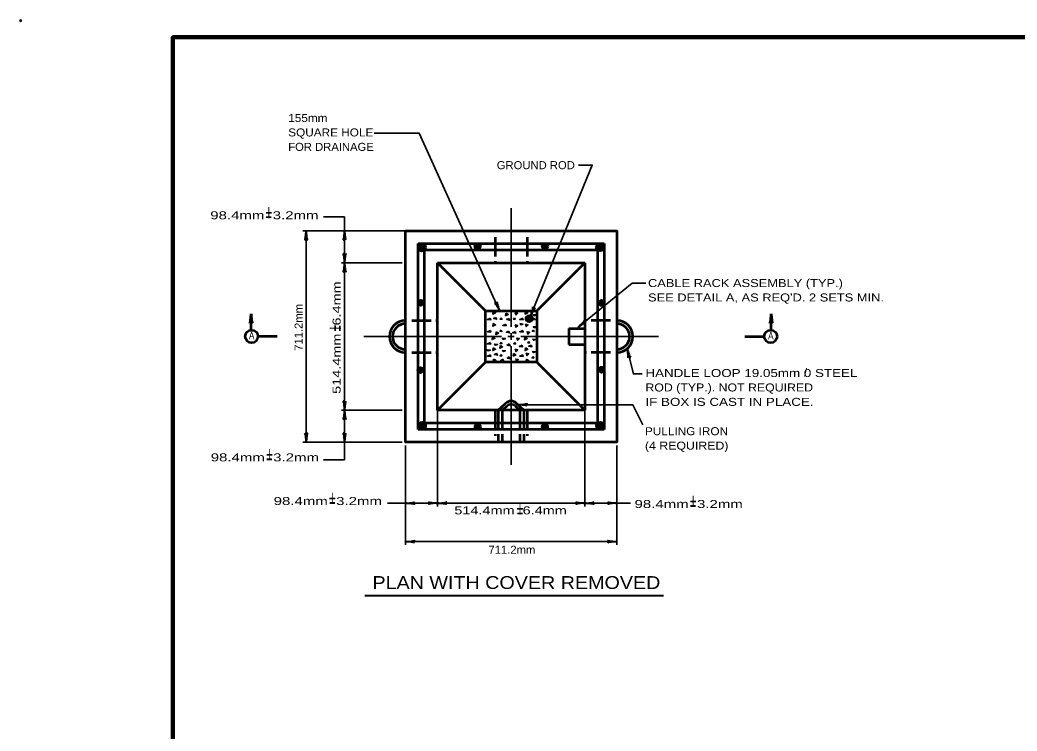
# Model space of a CAD drawing. Extents: x 918 to 1774, y -8 to 536.
# Drawn here: x 918 to 1291.6, y 270 to 536.2 of the extents above; entities that cross this region are included whole.
import ezdxf

# ---------------------------------------------------------------- set-up
doc = ezdxf.new("R2010")
doc.units = 0
doc.header["$LTSCALE"] = 1.2
doc.header["$PDMODE"] = 32
doc.header["$PDSIZE"] = 0.6
doc.linetypes.add('LONG_DASHED', pattern=[7.5, 6, -1.5])
doc.layers.add('1', color=7, linetype='Continuous', lineweight=35)

msp = doc.modelspace()

# ---------------------------------------------------------------- hatches: boundary and pattern name
at = {"layer": '1'}
for points in [[(1069.976, 451.064, 1), (1067.263, 451.064, 1)], [(1090.462, 451.497, 1), (1088.431, 451.497, 1)], [(1115.752, 451.548, 1), (1113.721, 451.548, 1)], [(1136.769, 451.092, 1), (1134.042, 451.092, 1)], [(1069.152, 430.315, 1), (1067.193, 430.315, 1)], [(1136.914, 430.261, 1), (1134.883, 430.261, 1)], [(1110.019, 424.368, 1), (1107.619, 424.368, 1)], [(1069.088, 405.105, 1), (1067.117, 405.105, 1)], [(1136.914, 405.247, 1), (1134.883, 405.247, 1)], [(1069.992, 384.305, 1), (1067.32, 384.305, 1)], [(1090.531, 383.884, 1), (1088.5, 383.884, 1)], [(1115.69, 383.857, 1), (1113.659, 383.857, 1)], [(1136.722, 384.319, 1), (1134.055, 384.319, 1)]]:
    msp.add_hatch(color=256, dxfattribs=at).paths.add_polyline_path(points)

# ---------------------------------------------------------------- linework, layer by layer
for p, q in [((1102.028, 465.692), (1102.028, 421.292)), ((1039.628, 462.502), (1031.703, 462.502)), ((1039.628, 445.292), (1039.628, 462.502)), ((1062.428, 457.292), (1024.028, 457.292)), ((1025.227, 457.292), (1025.227, 378.092)), ((1061.227, 445.292), (1038.428, 445.292)), ((1039.628, 445.292), (1039.628, 390.092)), ((1110.121, 425.918), (1111.379, 425.772)), ((1105.244, 422.513), (1106.502, 422.368)), ((1102.028, 418.892), (1102.028, 416.492)), ((1110.28, 421.408), (1111.525, 421.265)), ((1100.828, 417.692), (1103.227, 417.692)), ((1105.628, 417.692), (1157.227, 417.692)), ((1109.986, 416.71), (1111.237, 416.565)), ((1102.764, 410.352), (1102.899, 411.297)), ((1109.875, 412.12), (1111.122, 411.976)), ((1095.339, 408.3), (1095.476, 409.258)), ((1103.873, 408.962), (1104.072, 408.344)), ((1107.593, 408.265), (1107.728, 409.21)), ((1061.227, 390.092), (1038.428, 390.092)), ((1039.628, 390.092), (1039.628, 371.475)), ((1074.428, 390.092), (1074.428, 354.092)), ((1129.628, 390.092), (1129.628, 354.092)), ((1061.227, 378.092), (1024.028, 378.092)), ((1062.428, 376.892), (1062.428, 339.692)), ((1141.628, 376.892), (1141.628, 339.692)), ((1039.628, 371.475), (1031.703, 371.475)), ((1074.428, 355.292), (1055.658, 355.292)), ((1062.428, 340.892), (1141.628, 340.892))]:
    msp.add_line(p, q, dxfattribs=at)
at = {"layer": '1', "lineweight": 53}
for p, q in [((1067.227, 452.492), (1136.828, 452.492)), ((1067.227, 382.892), (1067.227, 452.492)), ((1136.828, 452.492), (1136.828, 382.892)), ((1069.628, 450.092), (1134.428, 450.092)), ((1069.628, 385.292), (1069.628, 450.092)), ((1134.428, 450.092), (1134.428, 385.292)), ((1074.428, 445.292), (1129.628, 445.292)), ((1074.428, 390.092), (1074.428, 445.292)), ((1074.428, 445.292), (1092.428, 427.292)), ((1129.628, 445.292), (1111.628, 427.292)), ((1004.606, 420.127), (1004.606, 426.127)), ((1199.449, 420.127), (1199.449, 426.127)), ((1123.628, 420.692), (1129.628, 420.692)), ((1123.628, 420.692), (1123.628, 414.692)), ((1014.428, 417.692), (1007.228, 417.692)), ((1123.628, 414.692), (1129.628, 414.692)), ((1189.628, 417.692), (1196.828, 417.692)), ((1074.428, 390.092), (1092.428, 408.092)), ((1129.628, 390.092), (1111.628, 408.092)), ((1097.227, 390.092), (1099.976, 392.669)), ((1106.828, 390.092), (1104.079, 392.669)), ((1129.628, 390.092), (1074.428, 390.092)), ((1098.727, 390.092), (1100.413, 391.624)), ((1103.642, 391.625), (1105.328, 390.092)), ((1134.428, 385.292), (1069.628, 385.292)), ((1136.828, 382.892), (1067.227, 382.892))]:
    msp.add_line(p, q, dxfattribs=at)
at = {"layer": '1', "linetype": 'LONG_DASHED', "lineweight": 53}
for p, q in [((1096.028, 454.892), (1096.028, 445.292)), ((1108.028, 454.892), (1108.028, 445.292)), ((1064.828, 423.692), (1074.428, 423.692)), ((1139.227, 423.692), (1129.628, 423.692)), ((1064.828, 411.692), (1074.428, 411.692)), ((1139.227, 411.692), (1129.628, 411.692)), ((1096.028, 390.092), (1096.028, 380.492)), ((1097.227, 390.092), (1097.227, 378.092)), ((1098.727, 390.092), (1098.727, 378.092)), ((1105.328, 390.092), (1105.328, 378.092)), ((1106.828, 390.092), (1106.828, 378.092)), ((1108.028, 390.092), (1108.028, 380.492))]:
    msp.add_line(p, q, dxfattribs=at)
at = {"layer": '1', "lineweight": 40}
msp.add_line((1047.216, 320.668), (1159.17, 320.668), dxfattribs=at)
at = {"layer": '1', "lineweight": 158}
msp.add_lwpolyline([(1766.999, 529.818), (975.299, 529.718), (975.399, 3.718)], dxfattribs=at)
at = {"layer": '1'}
for points in [[(1097.733, 427.292), (1067.59, 493.825), (1050.708, 493.825)], [(1109.317, 425.46), (1132.406, 481.895), (1127.321, 481.895)], [(1127.146, 421.196), (1147.358, 437.725), (1152.443, 437.725)], [(1095.338, 427.099), (1096.178, 426.619), (1095.146, 426.115), (1095.29, 427.123)], [(1100.133, 426.423), (1100.973, 425.943), (1099.941, 425.439), (1100.085, 426.447)], [(1103.858, 425.659), (1103.57, 426.619), (1104.506, 426.427), (1103.834, 425.707)], [(1107.434, 427.099), (1108.274, 426.619), (1107.242, 426.115), (1107.386, 427.123)], [(1111.379, 425.772), (1110.546, 425.478), (1110.114, 425.91)], [(1094.282, 424.507), (1093.154, 424.051), (1094.402, 423.907), (1094.282, 424.459)], [(1095.338, 422.539), (1096.178, 422.059), (1095.146, 421.555), (1095.29, 422.563)], [(1096.278, 424.815), (1095.486, 424.382), (1096.662, 424.167), (1096.23, 424.839)], [(1098.314, 424.675), (1097.858, 424.195), (1098.554, 424.147), (1098.314, 424.627)], [(1099.99, 422.307), (1098.862, 421.851), (1100.11, 421.707), (1099.99, 422.259)], [(1101.119, 424.452), (1100.327, 424.02), (1101.503, 423.804), (1101.071, 424.476)], [(1103.317, 424.725), (1102.861, 424.245), (1103.557, 424.197), (1103.317, 424.677)], [(1106.502, 422.356), (1105.668, 422.062), (1105.236, 422.494)], [(1106.378, 424.507), (1105.25, 424.051), (1106.498, 423.907), (1106.378, 424.459)], [(1107.729, 421.307), (1107.441, 422.267), (1108.377, 422.075), (1107.705, 421.355)], [(1110.686, 424.55), (1110.23, 424.07), (1110.926, 424.022), (1110.686, 424.502)], [(1094.282, 419.947), (1093.154, 419.491), (1094.402, 419.347), (1094.282, 419.899)], [(1096.461, 419.45), (1097.301, 418.97), (1096.269, 418.466), (1096.413, 419.474)], [(1098.314, 420.115), (1097.858, 419.635), (1098.554, 419.587), (1098.314, 420.067)], [(1101.074, 419.69), (1100.282, 419.258), (1101.458, 419.042), (1101.026, 419.714)], [(1103.676, 419.546), (1102.548, 419.09), (1103.796, 418.946), (1103.676, 419.498)], [(1103.858, 421.099), (1103.57, 422.059), (1104.506, 421.867), (1103.834, 421.147)], [(1106.378, 419.947), (1105.25, 419.491), (1106.498, 419.347), (1106.378, 419.899)], [(1108.303, 418.499), (1108.014, 419.459), (1108.951, 419.267), (1108.279, 418.547)], [(1110.41, 420.115), (1109.954, 419.635), (1110.65, 419.587), (1110.41, 420.067)], [(1111.525, 421.265), (1110.708, 420.976), (1110.276, 421.408)], [(1046.828, 417.692), (1056.428, 417.692), (1098.428, 417.692)], [(1094.282, 415.387), (1093.154, 414.931), (1094.402, 414.787), (1094.282, 415.339)], [(1095.087, 417.503), (1095.927, 417.023), (1094.895, 416.519), (1095.039, 417.527)], [(1098.314, 415.555), (1097.858, 415.075), (1098.554, 415.027), (1098.314, 415.507)], [(1101.318, 414.906), (1100.526, 414.474), (1101.702, 414.258), (1101.27, 414.93)], [(1103.46, 415.438), (1103.004, 414.958), (1103.699, 414.91), (1103.46, 415.39)], [(1104.503, 416.152), (1104.215, 417.112), (1105.151, 416.92), (1104.479, 416.2)], [(1107.233, 417.402), (1108.073, 416.922), (1107.041, 416.418), (1107.185, 417.426)], [(1108.71, 415.813), (1108.254, 415.333), (1108.95, 415.285), (1108.71, 415.765)], [(1111.237, 416.565), (1110.422, 416.278), (1109.99, 416.71)], [(1095.338, 413.419), (1096.178, 412.939), (1095.146, 412.435), (1095.29, 413.443)], [(1096.581, 411.377), (1095.789, 410.946), (1096.965, 410.73), (1096.533, 411.401)], [(1097.992, 414.3), (1098.832, 413.82), (1097.8, 413.316), (1097.944, 414.324)], [(1098.314, 410.995), (1097.858, 410.515), (1098.554, 410.467), (1098.314, 410.947)], [(1102.028, 414.092), (1102.028, 390.092), (1102.028, 369.692)], [(1102.914, 411.31), (1103.754, 410.83), (1102.775, 410.352)], [(1103.858, 411.979), (1103.57, 412.939), (1104.506, 412.747), (1103.834, 412.027)], [(1106.19, 414.449), (1105.062, 413.993), (1106.31, 413.849), (1106.19, 414.401)], [(1107.434, 413.419), (1108.274, 412.939), (1107.242, 412.435), (1107.386, 413.443)], [(1107.995, 410.455), (1107.707, 411.415), (1108.643, 411.223), (1107.971, 410.503)], [(1109.695, 414.473), (1108.567, 414.017), (1109.815, 413.873), (1109.685, 414.469)], [(1111.122, 411.976), (1110.307, 411.688), (1109.875, 412.12)], [(1145.524, 413.129), (1147.863, 403.665), (1151.118, 403.665)], [(1094.282, 410.827), (1093.154, 410.371), (1094.402, 410.227), (1094.282, 410.779)], [(1095.479, 409.259), (1096.319, 408.779), (1095.339, 408.3)], [(1098.962, 409.151), (1098.17, 408.719), (1099.346, 408.503), (1098.914, 409.175)], [(1101.343, 410.02), (1100.551, 409.588), (1101.727, 409.372), (1101.295, 410.044)], [(1103.868, 408.959), (1103.782, 409.246), (1104.718, 409.054), (1104.053, 408.342)], [(1106.378, 410.827), (1105.25, 410.371), (1106.498, 410.227), (1106.368, 410.823)], [(1107.731, 409.223), (1108.571, 408.743), (1107.593, 408.265)], [(1107.731, 409.223), (1108.571, 408.743), (1107.593, 408.265)], [(1110.258, 410.163), (1109.802, 409.683), (1110.497, 409.635), (1110.242, 410.146)], [(1104.612, 392.17), (1147.66, 392.068), (1151.321, 384.642)], [(1074.428, 355.292), (1129.628, 355.292), (1146.78, 355.292)]]:
    msp.add_lwpolyline(points, dxfattribs=at)
at = {"layer": '1', "lineweight": 53}
for points in [[(1062.428, 457.292), (1141.628, 457.292), (1141.628, 378.092), (1062.428, 378.092)], [(1092.428, 427.292), (1111.628, 427.292), (1111.628, 408.092), (1092.428, 408.092)]]:
    msp.add_lwpolyline(points, close=True, dxfattribs=at)
msp.add_lwpolyline([(1129.628, 445.292), (1129.628, 417.692), (1129.628, 390.092)], dxfattribs=at)
at = {"layer": '1'}
for points in [[(1095.71, 414.876), (1096.958, 414.732), (1096.142, 414.444)], [(1098.65, 417.043), (1099.898, 416.899), (1099.082, 416.611)], [(1092.948, 412.756), (1094.196, 412.612), (1093.38, 412.324)], [(1098.65, 412.483), (1099.898, 412.339), (1099.082, 412.051)]]:
    msp.add_lwpolyline(points, close=True, dxfattribs=at)
at = {"layer": '1', "lineweight": 53}
for centre, radius in [((1068.619, 451.064), 1.356), ((1089.447, 451.497), 1.016), ((1114.737, 451.548), 1.016), ((1135.406, 451.092), 1.363), ((1068.172, 430.315), 0.979), ((1135.898, 430.261), 1.016), ((1108.819, 424.368), 1.2), ((1004.787, 417.698), 2.4), ((1199.268, 417.698), 2.4), ((1068.103, 405.105), 0.985), ((1135.898, 405.247), 1.016), ((1068.656, 384.305), 1.336), ((1089.515, 383.884), 1.016), ((1114.675, 383.857), 1.016), ((1135.389, 384.319), 1.333)]:
    msp.add_circle(centre, radius, dxfattribs=at)
for centre, radius, start, end in [((1062.428, 417.692), 6, 90, 270), ((1062.428, 417.692), 4.8, 90, 270), ((1141.628, 417.692), 6, 270, 90), ((1141.628, 417.692), 4.8, 270, 90), ((1102.027, 390.48), 3, 46.84755, 133.1524), ((1102.028, 389.849), 2.4, 47.72631, 132.27692)]:
    msp.add_arc(centre, radius, start, end, dxfattribs=at)
at = {"layer": '1', "lineweight": 40}
for centre, major_axis, ratio, start_param, end_param in [((1024.974, 455.948), (0.211, 2.108), 0.07063, 3.1407148, 5.41811), ((1025.559, 455.983), (-0.187, 2.143), 0.122415, 0.8963533, 3.1415927), ((1039.374, 455.948), (0.211, 2.108), 0.07063, 3.1407148, 5.41811), ((1039.374, 455.948), (0.211, 2.108), 0.07063, 3.1407148, 5.41811), ((1039.959, 455.983), (-0.187, 2.143), 0.122415, 0.8963533, 3.1415927), ((1039.959, 455.983), (-0.187, 2.143), 0.122415, 0.8963533, 3.1415927), ((1039.296, 446.602), (0.187, -2.143), 0.122415, 0.8963533, 3.1415927), ((1039.296, 446.602), (0.187, -2.143), 0.122415, 0.8963533, 3.1415927), ((1039.881, 446.637), (-0.211, -2.108), 0.07063, 3.1407148, 5.41811), ((1039.881, 446.637), (-0.211, -2.108), 0.07063, 3.1407148, 5.41811), ((1039.374, 443.948), (0.211, 2.108), 0.07063, 3.1407148, 5.41811), ((1039.374, 443.948), (0.211, 2.108), 0.07063, 3.1407148, 5.41811), ((1039.959, 443.983), (-0.187, 2.143), 0.122415, 0.8963533, 3.1415927), ((1039.959, 443.983), (-0.187, 2.143), 0.122415, 0.8963533, 3.1415927), ((1096.891, 428.348), (1.055, -1.875), 0.122415, 0.8963533, 3.1415927), ((1096.891, 428.348), (1.055, -1.875), 0.122415, 0.8963533, 3.1415927), ((1097.409, 428.622), (-0.678, 2.007), 0.07063, 6.2823074, 8.5597026), ((1097.409, 428.622), (-0.678, 2.007), 0.07063, 6.2823074, 8.5597026), ((1109.506, 426.797), (-0.638, -2.054), 0.122415, 0.8963533, 3.1415927), ((1110.061, 426.608), (0.993, 1.871), 0.07063, 6.2823074, 8.5597026), ((1127.95, 422.282), (-1.54, -1.502), 0.122415, 0.8963533, 3.1415927), ((1127.95, 422.282), (-1.54, -1.502), 0.122415, 0.8963533, 3.1415927), ((1128.347, 421.851), (1.765, 1.171), 0.07063, 6.2823074, 8.5597026), ((1128.347, 421.851), (1.765, 1.171), 0.07063, 6.2823074, 8.5597026), ((1145.6, 411.763), (-0.301, 2.097), 0.07063, 3.1407148, 5.41811), ((1145.6, 411.763), (-0.301, 2.097), 0.07063, 3.1407148, 5.41811), ((1146.16, 411.938), (-0.696, 2.035), 0.122415, 0.8963533, 3.1415927), ((1146.16, 411.938), (-0.696, 2.035), 0.122415, 0.8963533, 3.1415927), ((1039.296, 391.402), (0.187, -2.143), 0.122415, 0.8963533, 3.1415927), ((1039.296, 391.402), (0.187, -2.143), 0.122415, 0.8963533, 3.1415927), ((1039.881, 391.437), (-0.211, -2.108), 0.07063, 3.1407148, 5.41811), ((1039.881, 391.437), (-0.211, -2.108), 0.07063, 3.1407148, 5.41811), ((1105.922, 392.498), (-2.143, -0.182), 0.122415, 0.8963533, 3.1415927), ((1039.374, 388.748), (0.211, 2.108), 0.07063, 3.1407148, 5.41811), ((1039.374, 388.748), (0.211, 2.108), 0.07063, 3.1407148, 5.41811), ((1039.959, 388.783), (-0.187, 2.143), 0.122415, 0.8963533, 3.1415927), ((1039.959, 388.783), (-0.187, 2.143), 0.122415, 0.8963533, 3.1415927), ((1105.956, 391.913), (2.107, -0.216), 0.07063, 6.2823074, 8.5597026), ((1024.896, 379.402), (0.187, -2.143), 0.122415, 0.8963533, 3.1415927), ((1024.896, 379.402), (0.187, -2.143), 0.122415, 0.8963533, 3.1415927), ((1025.481, 379.437), (-0.211, -2.108), 0.07063, 3.1407148, 5.41811), ((1025.481, 379.437), (-0.211, -2.108), 0.07063, 3.1407148, 5.41811), ((1039.296, 379.402), (0.187, -2.143), 0.122415, 0.8963533, 3.1415927), ((1039.296, 379.402), (0.187, -2.143), 0.122415, 0.8963533, 3.1415927), ((1039.881, 379.437), (-0.211, -2.108), 0.07063, 3.1407148, 5.41811), ((1039.881, 379.437), (-0.211, -2.108), 0.07063, 3.1407148, 5.41811), ((1063.772, 355.038), (-2.108, 0.211), 0.07063, 3.1407148, 5.41811), ((1063.772, 355.038), (-2.108, 0.211), 0.07063, 3.1407148, 5.41811), ((1063.737, 355.624), (-2.143, -0.187), 0.122415, 0.8963533, 3.1415927), ((1063.737, 355.624), (-2.143, -0.187), 0.122415, 0.8963533, 3.1415927), ((1073.118, 354.961), (2.143, 0.187), 0.122415, 0.8963533, 3.1415927), ((1073.118, 354.961), (2.143, 0.187), 0.122415, 0.8963533, 3.1415927), ((1073.083, 355.546), (2.108, -0.211), 0.07063, 3.1407148, 5.41811), ((1073.083, 355.546), (2.108, -0.211), 0.07063, 3.1407148, 5.41811), ((1075.772, 355.038), (-2.108, 0.211), 0.07063, 3.1407148, 5.41811), ((1075.772, 355.038), (-2.108, 0.211), 0.07063, 3.1407148, 5.41811), ((1075.737, 355.624), (-2.143, -0.187), 0.122415, 0.8963533, 3.1415927), ((1075.737, 355.624), (-2.143, -0.187), 0.122415, 0.8963533, 3.1415927), ((1128.318, 354.961), (2.143, 0.187), 0.122415, 0.8963533, 3.1415927), ((1128.318, 354.961), (2.143, 0.187), 0.122415, 0.8963533, 3.1415927), ((1128.283, 355.546), (2.108, -0.211), 0.07063, 3.1407148, 5.41811), ((1128.283, 355.546), (2.108, -0.211), 0.07063, 3.1407148, 5.41811), ((1130.972, 355.038), (-2.108, 0.211), 0.07063, 3.1407148, 5.41811), ((1130.972, 355.038), (-2.108, 0.211), 0.07063, 3.1407148, 5.41811), ((1130.937, 355.624), (-2.143, -0.187), 0.122415, 0.8963533, 3.1415927), ((1130.937, 355.624), (-2.143, -0.187), 0.122415, 0.8963533, 3.1415927), ((1140.318, 354.961), (2.143, 0.187), 0.122415, 0.8963533, 3.1415927), ((1140.318, 354.961), (2.143, 0.187), 0.122415, 0.8963533, 3.1415927), ((1140.283, 355.546), (2.108, -0.211), 0.07063, 3.1407148, 5.41811), ((1140.283, 355.546), (2.108, -0.211), 0.07063, 3.1407148, 5.41811), ((1063.772, 340.638), (-2.108, 0.211), 0.07063, 3.1407148, 5.41811), ((1063.737, 341.224), (-2.143, -0.187), 0.122415, 0.8963533, 3.1415927), ((1140.318, 340.561), (2.143, 0.187), 0.122415, 0.8963533, 3.1415927), ((1140.318, 340.561), (2.143, 0.187), 0.122415, 0.8963533, 3.1415927), ((1140.283, 341.146), (2.108, -0.211), 0.07063, 3.1407148, 5.41811), ((1140.283, 341.146), (2.108, -0.211), 0.07063, 3.1407148, 5.41811)]:
    msp.add_ellipse(centre, major_axis=major_axis, ratio=ratio, start_param=start_param, end_param=end_param, dxfattribs=at)
at = {"layer": '1', "lineweight": 53}
for centre, major_axis, ratio, start_param, end_param in [((1004.352, 424.782), (0.211, 2.108), 0.07063, 3.1407148, 5.41811), ((1004.937, 424.817), (-0.187, 2.143), 0.122415, 0.8963533, 3.1415927), ((1199.118, 424.817), (0.187, 2.143), 0.122415, 3.1415927, 5.386832), ((1199.703, 424.782), (-0.211, 2.108), 0.07063, 0.8650754, 3.1424706)]:
    msp.add_ellipse(centre, major_axis=major_axis, ratio=ratio, start_param=start_param, end_param=end_param, dxfattribs=at)
at = {"layer": '1'}
msp.add_point((918.299, 535.918), dxfattribs=at)

# ---------------------------------------------------------------- texts
for s, height, width, p in [('155mm', 3, 1.1, (1018.514, 498.006)), ('SQUARE HOLE', 3, 1.1, (1018.514, 492.606)), ('FOR DRAINAGE', 3, 1.05, (1018.514, 487.206)), ('GROUND ROD', 3, 1.05, (1096.648, 480.346)), ('98.4mm  3.2mm', 3, 1.4, (989.291, 461.586)), ('CABLE RACK ASSEMBLY (TYP.)', 3, 1.2, (1153.317, 436.207)), ("SEE DETAIL A, AS REQ'D. 2 SETS MIN.", 3, 1.2, (1153.317, 430.807)), ('A', 2.76, 0.85, (1003.752, 416.641)), ('A', 2.76, 0.85, (1198.284, 416.585)), ('HANDLE LOOP 19.05mm 0 STEEL', 3, 1.25, (1152.351, 402.516)), ('ROD (TYP.). NOT REQUIRED', 3, 1.15, (1152.351, 397.116)), ('IF BOX IS CAST IN PLACE.', 3, 1.25, (1152.351, 391.716)), ('PULLING IRON', 3, 1.1, (1152.172, 380.727)), ('(4 REQUIRED)', 3, 1.15, (1152.172, 375.327)), ('98.4mm  3.2mm', 3, 1.4, (989.476, 370.937)), ('98.4mm  3.2mm', 3, 1.4, (1013.062, 354.59)), ('98.4mm  3.2mm', 3, 1.4, (1148.259, 353.476)), ('514.4mm  6.4mm', 3, 1.35, (1080.757, 351.098)), ('711.2mm', 3, 1.05, (1093.534, 336.359)), ('PLAN WITH COVER REMOVED', 4.8, 1.15, (1050.072, 323.168))]:
    msp.add_text(s, height=height, dxfattribs=dict(at, width=width)).set_placement(p)
for s, height, rotation, width, p in [('+', 6, 180, 0.55, (1012.566, 466.958)), ('514.4mm  6.4mm', 3, 90, 1.35, (1038.139, 396.21)), ('711.2mm', 3, 90, 1.05, (1023.903, 412.328)), ('+', 6, 270, 0.55, (1033.224, 422.101)), ('+', 6, 180, 0.55, (1012.752, 376.309)), ('+', 6, 180, 0.55, (1036.337, 359.962)), ('+', 6, 180, 0.55, (1106.648, 356.013)), ('+', 6, 180, 0.55, (1171.535, 358.848))]:
    msp.add_text(s, height=height, rotation=rotation, dxfattribs=dict(at, width=width)).set_placement(p)
for rotation, p in [(180, (1012.566, 464.669)), (270, (1035.512, 422.101)), (180, (1012.751, 374.02)), (180, (1036.337, 357.674)), (180, (1106.648, 353.725)), (180, (1171.535, 356.559))]:
    msp.add_text('-', height=6, rotation=rotation, dxfattribs=at).set_placement(p)
msp.add_text('/', height=3, dxfattribs=at).set_placement((1211.786, 402.702))

doc.saveas('drawing.dxf')
